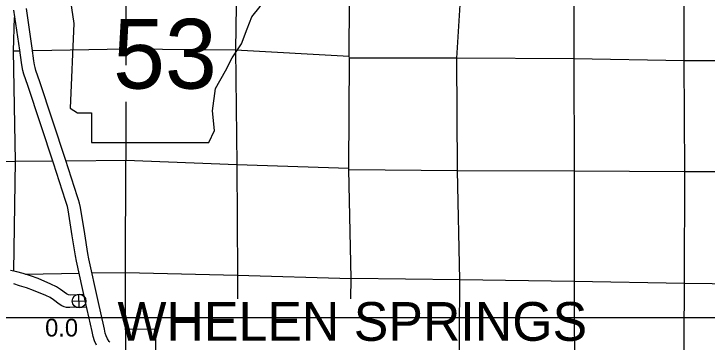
# Model space of a CAD drawing. Extents: x 369523 to 838377, y 495025 to 936819.
# Drawn here: x 563289 to 596328, y 673361 to 689027 of the extents above; entities that cross this region are included whole.
import ezdxf

# ---------------------------------------------------------------- set-up
doc = ezdxf.new("R2010")
doc.units = 0
for name, color, linetype in [('21', 7, 'Continuous'), ('22', 7, 'Continuous'), ('DSN_BRDG_Annotation', 7, 'Continuous'), ('DSN_DRFT_Common-Annotations', 7, 'Continuous'), ('Level 1', 7, 'Continuous'), ('Level 15', 7, 'Continuous'), ('Level 2', 7, 'Continuous'), ('Level 22', 7, 'Continuous')]:
    doc.layers.add(name, color=color, linetype=linetype)

msp = doc.modelspace()

# ---------------------------------------------------------------- linework, layer by layer
at = {"layer": '21'}
msp.add_line((542697, 674544), (838377, 674544), dxfattribs=at)
at = {"layer": '22'}
msp.add_lwpolyline([(565743, 691236), (566142, 688572), (565965, 684531), (566320, 684308), (566986, 684308), (566986, 682887), (572582, 682887), (572848, 683465), (572759, 684397), (572893, 685463), (573381, 686307), (573692, 686929), (574136, 687595), (574403, 688305), (574625, 688883), (575024, 689371), (575113, 689682), (574935, 689904), (573559, 689904), (573870, 690526), (573914, 690925), (573730, 691232)], close=True, dxfattribs=at)
at = {"layer": 'DSN_DRFT_Common-Annotations'}
for p, q in [((566404, 674994), (566389, 675645)), ((566071, 675312), (566722, 675327))]:
    msp.add_line(p, q, dxfattribs=at)
msp.add_circle((566396, 675320), 326, dxfattribs=at)
at = {"layer": 'Level 1'}
for points in [[(563566, 687299), (563291, 689199)], [(564160, 687385), (563885, 689287)], [(567235, 673221), (567139, 673427), (567061, 673624), (567020, 673862), (566700, 675272), (566280, 677220), (566227, 677475), (566074, 678441), (565877, 679668), (565838, 679840), (565799, 679980), (565754, 680119), (565180, 681896), (563952, 685601), (563766, 686152), (563720, 686320), (563681, 686493), (563650, 686708), (563566, 687300)], [(567866, 673360), (567839, 673397), (567759, 673516), (567690, 673664), (567642, 673786), (567609, 673979), (567286, 675402), (566867, 677345), (566817, 677584), (566666, 678536), (566467, 679782), (566420, 679988), (566374, 680152), (566326, 680303), (565751, 682083), (564521, 685791), (564340, 686328), (564302, 686466), (564272, 686601), (564244, 686793), (564160, 687384)], [(566626, 675628), (565965, 675610), (565896, 675615), (565889, 675617), (565866, 675628), (565800, 675673), (565515, 675874), (565323, 676007), (565051, 676134), (564453, 676392), (564075, 676528), (563733, 676630), (563433, 676718), (563135, 676787)], [(566752, 675031), (565950, 675010), (565795, 675021), (565690, 675050), (565572, 675101), (565456, 675181), (565171, 675383), (565024, 675485), (564805, 675586), (564232, 675834), (563888, 675958), (563563, 676054), (563281, 676137)]]:
    msp.add_lwpolyline(points, dxfattribs=at)
at = {"layer": 'Level 15'}
for points in [[(579270, 687010), (579307, 692315), (579310, 692379), (579248, 697636), (579374, 702872), (579369, 702934), (579349, 708170), (579351, 708274), (579357, 713634), (579348, 713672), (579404, 718915), (579393, 718967), (579333, 724212), (579338, 724254), (579369, 729487)], [(579345, 675431), (579363, 676395), (579255, 681603), (579251, 681661), (579281, 686914), (579270, 687010)]]:
    msp.add_lwpolyline(points, dxfattribs=at)
at = {"layer": 'Level 2'}
msp.add_lwpolyline([(570041, 673975), (570046, 671944), (570448, 671701), (570466, 671469), (570463, 671362), (570140, 671268), (570344, 670630), (568622, 670654), (567902, 670664), (567906, 671293), (567914, 672679), (568627, 672692), (568624, 674003), (570041, 673975)], dxfattribs=at)
at = {"layer": 'Level 22'}
for points in [[(568631, 687359), (568658, 692691), (568766, 697804)], [(574083, 697711), (573932, 692623), (573854, 687312)], [(584406, 686909), (584729, 692277), (584600, 697601)], [(589966, 697533), (589969, 692247), (589971, 686884)], [(595226, 686791), (595238, 692120), (595142, 697481)], [(563272, 687264), (563319, 688855)], [(563365, 681990), (563272, 687264), (563556, 687269)], [(564209, 687281), (568631, 687359), (568632, 686574)], [(568631, 687359), (573854, 687312), (579270, 687010)], [(573854, 687312), (573922, 681839), (573952, 676552), (573954, 675431)], [(605958, 686705), (600612, 686778), (595226, 686791), (589971, 686884), (584406, 686909), (579281, 686914)], [(584503, 665720), (584515, 671055), (584537, 676328), (584437, 681553), (584406, 686909)], [(589971, 686884), (589989, 681541), (589999, 676249), (590001, 670994), (589897, 665633)], [(595264, 665568), (595211, 670897), (595246, 676160), (595266, 681506), (595226, 686791)], [(568632, 684832), (568633, 682051)], [(547556, 682136), (552818, 681889), (558105, 681881), (563365, 681990), (565156, 682011)], [(563293, 676760), (563365, 681990)], [(565777, 682018), (568633, 682051)], [(568614, 673942), (568612, 676687), (568633, 682051)], [(568633, 682051), (573922, 681839), (579251, 681661)], [(579255, 681603), (584437, 681553), (589989, 681541), (595266, 681506), (600576, 681512), (605992, 681400)], [(563827, 676611), (566411, 676652)], [(567029, 676662), (568612, 676687)], [(568612, 676687), (573952, 676552), (579363, 676395)], [(605946, 676006), (600536, 676091), (595246, 676160), (589999, 676249), (584537, 676328), (579363, 676395)]]:
    msp.add_lwpolyline(points, dxfattribs=at)

# ---------------------------------------------------------------- texts
at = {"layer": '22'}
msp.add_text('53', height=3326.4, dxfattribs=at).set_placement((568015, 685460))
at = {"layer": 'DSN_BRDG_Annotation'}
msp.add_text('0.0', height=844.8, dxfattribs=at).set_placement((564779, 673631))
at = {"layer": 'DSN_DRFT_Common-Annotations'}
msp.add_text('WHELEN SPRINGS', height=1848, dxfattribs=at).set_placement((568228, 673426))

doc.saveas('drawing.dxf')
